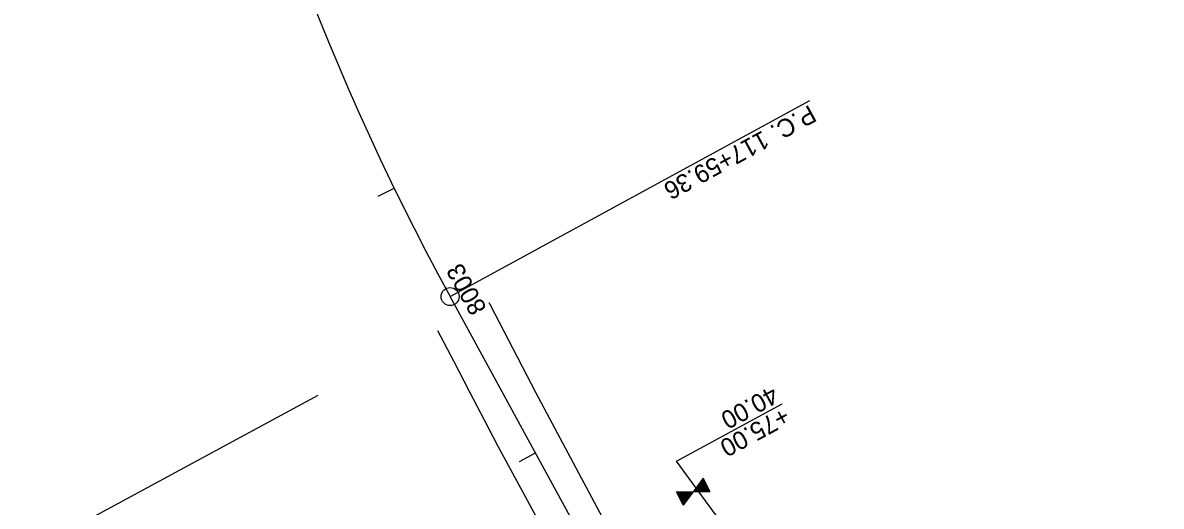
# Model space of a CAD drawing. Extents: x 1627557 to 1636561, y 783843 to 794002.
# Drawn here: x 1627667.9 to 1628047.3, y 785301.4 to 785462.7 of the extents above; entities that cross this region are included whole.
import ezdxf

# ---------------------------------------------------------------- set-up
doc = ezdxf.new("R2010")
doc.units = 0
for name, color, linetype in [('GATE', 7, 'Continuous'), ('Point Numbers', 7, 'Continuous'), ('R_Horz Alg', 7, 'Continuous'), ('R_Horz Alg Annot', 7, 'Continuous'), ('R_Proposed Road', 7, 'Continuous'), ('R_Temp Const Easement', 7, 'Continuous'), ('R_Temp Easement Annot', 7, 'Continuous'), ('Transition Dimensions', 7, 'Continuous')]:
    doc.layers.add(name, color=color, linetype=linetype)

msp = doc.modelspace()

# ---------------------------------------------------------------- linework, layer by layer
at = {"layer": 'GATE'}
for p, q in [((1627892.18, 785307.43), (1627892.77, 785306.29)), ((1627892.24, 785307.52), (1627892.88, 785306.29)), ((1627892.31, 785307.61), (1627892.99, 785306.29)), ((1627892.38, 785307.7), (1627893.1, 785306.29)), ((1627892.44, 785307.79), (1627893.21, 785306.29)), ((1627892.51, 785307.88), (1627893.33, 785306.29)), ((1627892.57, 785307.97), (1627893.44, 785306.3)), ((1627892.64, 785308.06), (1627893.55, 785306.3)), ((1627892.71, 785308.15), (1627893.66, 785306.3)), ((1627892.77, 785308.24), (1627893.77, 785306.3)), ((1627892.84, 785308.33), (1627893.89, 785306.3)), ((1627892.9, 785308.42), (1627894, 785306.3)), ((1627892.97, 785308.51), (1627894.11, 785306.3)), ((1627893.03, 785308.6), (1627894.22, 785306.31)), ((1627893.1, 785308.69), (1627894.33, 785306.31)), ((1627893.17, 785308.78), (1627894.44, 785306.31)), ((1627893.23, 785308.87), (1627894.56, 785306.31)), ((1627893.3, 785308.97), (1627894.67, 785306.31)), ((1627893.36, 785309.06), (1627894.78, 785306.31)), ((1627893.43, 785309.15), (1627894.89, 785306.31)), ((1627893.5, 785309.24), (1627895, 785306.32)), ((1627893.56, 785309.33), (1627895.11, 785306.32)), ((1627893.63, 785309.42), (1627895.23, 785306.32)), ((1627893.69, 785309.51), (1627895.34, 785306.32)), ((1627893.76, 785309.6), (1627895.45, 785306.32)), ((1627893.83, 785309.69), (1627895.56, 785306.32)), ((1627893.89, 785309.78), (1627895.67, 785306.32)), ((1627893.96, 785309.87), (1627895.79, 785306.33)), ((1627894.02, 785309.96), (1627895.9, 785306.33)), ((1627894.09, 785310.05), (1627896.01, 785306.33)), ((1627894.16, 785310.14), (1627896.12, 785306.33)), ((1627894.22, 785310.23), (1627896.23, 785306.33)), ((1627894.29, 785310.32), (1627896.34, 785306.33)), ((1627894.35, 785310.41), (1627896.46, 785306.33)), ((1627894.42, 785310.5), (1627896.57, 785306.34)), ((1627894.49, 785310.59), (1627896.68, 785306.34)), ((1627894.55, 785310.68), (1627896.79, 785306.34)), ((1627894.62, 785310.77), (1627896.9, 785306.34)), ((1627885.82, 785306.2), (1627888.08, 785301.82)), ((1627885.93, 785306.2), (1627888.15, 785301.91)), ((1627886.04, 785306.2), (1627888.21, 785302)), ((1627886.16, 785306.2), (1627888.28, 785302.09)), ((1627886.27, 785306.21), (1627888.34, 785302.18)), ((1627886.38, 785306.21), (1627888.41, 785302.27)), ((1627886.49, 785306.21), (1627888.48, 785302.36)), ((1627886.6, 785306.21), (1627888.54, 785302.45)), ((1627886.71, 785306.21), (1627888.61, 785302.54)), ((1627886.83, 785306.21), (1627888.67, 785302.63)), ((1627886.94, 785306.21), (1627888.74, 785302.72)), ((1627887.05, 785306.21), (1627888.8, 785302.81)), ((1627887.16, 785306.22), (1627888.87, 785302.9)), ((1627887.27, 785306.22), (1627888.94, 785302.99)), ((1627887.38, 785306.22), (1627889, 785303.08)), ((1627887.5, 785306.22), (1627889.07, 785303.17)), ((1627887.61, 785306.22), (1627889.13, 785303.26)), ((1627887.72, 785306.22), (1627889.2, 785303.35)), ((1627887.83, 785306.22), (1627889.27, 785303.44)), ((1627887.94, 785306.23), (1627889.33, 785303.53)), ((1627888.06, 785306.23), (1627889.4, 785303.63)), ((1627888.17, 785306.23), (1627889.46, 785303.72)), ((1627888.28, 785306.23), (1627889.53, 785303.81)), ((1627888.39, 785306.23), (1627889.6, 785303.9)), ((1627888.5, 785306.23), (1627889.66, 785303.99)), ((1627888.61, 785306.23), (1627889.73, 785304.08)), ((1627888.73, 785306.24), (1627889.79, 785304.17)), ((1627888.84, 785306.24), (1627889.86, 785304.26)), ((1627888.95, 785306.24), (1627889.93, 785304.35)), ((1627889.06, 785306.24), (1627889.99, 785304.44)), ((1627889.17, 785306.24), (1627890.06, 785304.53)), ((1627889.29, 785306.24), (1627890.12, 785304.62)), ((1627889.4, 785306.24), (1627890.19, 785304.71)), ((1627889.51, 785306.25), (1627890.26, 785304.8)), ((1627889.62, 785306.25), (1627890.32, 785304.89)), ((1627889.73, 785306.25), (1627890.39, 785304.98)), ((1627889.84, 785306.25), (1627890.45, 785305.07)), ((1627889.96, 785306.25), (1627890.52, 785305.16)), ((1627890.07, 785306.25), (1627890.59, 785305.25)), ((1627890.18, 785306.25), (1627890.65, 785305.34)), ((1627890.29, 785306.26), (1627890.72, 785305.43)), ((1627890.4, 785306.26), (1627890.78, 785305.52)), ((1627890.52, 785306.26), (1627890.85, 785305.61)), ((1627890.63, 785306.26), (1627890.92, 785305.7)), ((1627890.74, 785306.26), (1627890.98, 785305.79)), ((1627890.85, 785306.26), (1627891.05, 785305.88)), ((1627890.96, 785306.26), (1627891.11, 785305.97)), ((1627891.07, 785306.27), (1627891.18, 785306.06)), ((1627891.19, 785306.27), (1627891.24, 785306.15)), ((1627891.3, 785306.27), (1627891.31, 785306.24)), ((1627891.39, 785306.35), (1627891.43, 785306.27)), ((1627891.45, 785306.44), (1627891.54, 785306.27)), ((1627891.52, 785306.53), (1627891.65, 785306.27)), ((1627891.58, 785306.62), (1627891.76, 785306.27)), ((1627891.65, 785306.71), (1627891.87, 785306.28)), ((1627891.72, 785306.8), (1627891.98, 785306.28)), ((1627891.78, 785306.89), (1627892.1, 785306.28)), ((1627891.85, 785306.98), (1627892.21, 785306.28)), ((1627891.91, 785307.07), (1627892.32, 785306.28)), ((1627891.98, 785307.16), (1627892.43, 785306.28)), ((1627892.05, 785307.25), (1627892.54, 785306.28)), ((1627892.11, 785307.34), (1627892.66, 785306.29))]:
    msp.add_line(p, q, dxfattribs=at)
for points in [[(1627894.63, 785310.78), (1627891.33, 785306.27), (1627896.92, 785306.34)], [(1627885.74, 785306.2), (1627891.33, 785306.27), (1627888.03, 785301.76)]]:
    msp.add_lwpolyline(points, close=True, dxfattribs=at)
at = {"layer": 'R_Horz Alg'}
msp.add_line((1628236.53, 784589.68), (1627810.31, 785371.39), dxfattribs=at)
msp.add_circle((1627810.31, 785371.39), 3, dxfattribs=at)
msp.add_arc((1628574.42, 785788.02), 870.32, 172.69845, 208.60097, dxfattribs=at)
at = {"layer": 'R_Horz Alg Annot'}
for points in [[(1627810.31, 785371.39), (1627930.21, 785436.77)], [(1627786.3, 785404.89), (1627791.7, 785407.51)], [(1627833.46, 785316.4), (1627838.73, 785319.27)]]:
    msp.add_lwpolyline(points, dxfattribs=at)
at = {"layer": 'R_Proposed Road'}
for points in [[(1627894.59, 785235.48), (1627885.25, 785252.85), (1627875.61, 785270.75), (1627866, 785288.64), (1627862.81, 785294.6), (1627853.24, 785312.47), (1627838.98, 785339.15), (1627823.77, 785368.51), (1627823.35, 785369.33)], [(1627877.63, 785226.59), (1627868.35, 785243.68), (1627855.63, 785267.1), (1627836.09, 785303.33), (1627826.27, 785321.55), (1627822.02, 785329.68), (1627816.77, 785339.74), (1627811.51, 785349.81), (1627806.2, 785359.98)]]:
    msp.add_lwpolyline(points, dxfattribs=at)
at = {"layer": 'R_Temp Const Easement'}
msp.add_line((1627930.5, 785255.41), (1627885.81, 785316.47), dxfattribs=at)
at = {"layer": 'R_Temp Easement Annot'}
msp.add_lwpolyline([(1627885.81, 785316.47), (1627920.93, 785335.62)], dxfattribs=at)
at = {"layer": 'Transition Dimensions'}
msp.add_line((1627766.27, 785338.38), (1627667.91, 785285.17), dxfattribs=at)

# ---------------------------------------------------------------- texts
at = {"layer": 'Point Numbers'}
msp.add_text('8003', height=6, rotation=119.1051, dxfattribs=at).set_placement((1627822.68, 785367.42))
at = {"layer": 'R_Horz Alg Annot'}
msp.add_text('P.C. 117+59.36', height=6, rotation=208.601, dxfattribs=at).set_placement((1627930.1, 785435.48))
at = {"layer": 'R_Temp Easement Annot'}
for s, p in [('40.00', (1627917.58, 785341.77)), ('+75.00', (1627921.41, 785334.74))]:
    msp.add_text(s, height=6, rotation=208.601, dxfattribs=at).set_placement(p)

doc.saveas('drawing.dxf')
